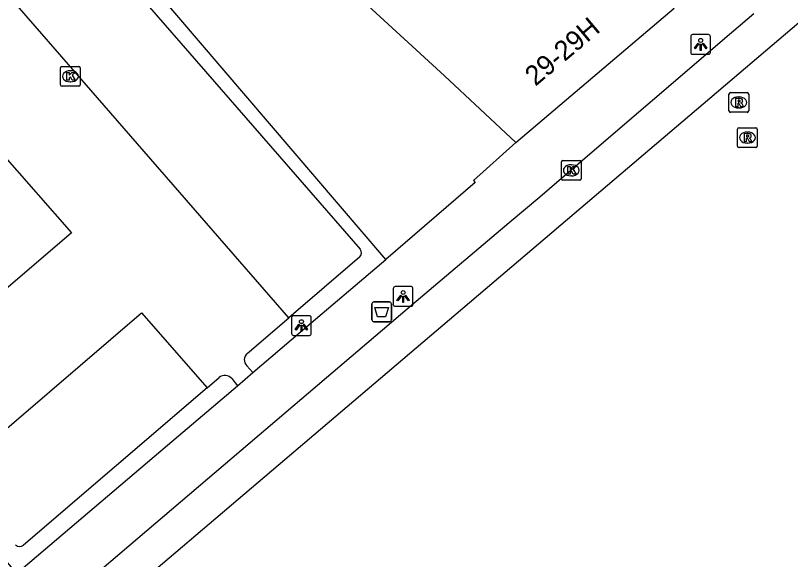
# Model space of a CAD drawing. Extents: x 161772 to 163123, y 383092 to 383917.
# Drawn here: x 162225.14 to 162264.38, y 383158.41 to 383185.94 of the extents above; entities that cross this region are included whole.
import ezdxf

# ---------------------------------------------------------------- set-up
doc = ezdxf.new("R2010")
doc.units = 0
for name, color, linetype in [('IMGEO_Afvalbak', 7, 'Continuous'), ('IMGEO_Groenvoorziening', 7, 'Continuous'), ('IMGEO_Hek', 7, 'Continuous'), ('IMGEO_Kolk', 7, 'Continuous'), ('IMGEO_Lichtpunt', 7, 'Continuous'), ('IMGEO_Pand', 7, 'Continuous'), ('IMGEO_Pand_nummerreeks', 7, 'Continuous'), ('IMGEO_Parkeervlak_open', 7, 'Continuous'), ('IMGEO_Rijbaan_lokaal_gesloten', 7, 'Continuous'), ('IMGEO_Rijbaan_lokaal_open', 7, 'Continuous'), ('IMGEO_Rioolput', 7, 'Continuous'), ('IMGEO_Voetpad_open', 7, 'Continuous')]:
    doc.layers.add(name, color=color, linetype=linetype)

msp = doc.modelspace()

# ---------------------------------------------------------------- linework, layer by layer
at = {"layer": 'IMGEO_Afvalbak'}
for p, q in [((162243.185, 383170.546), (162243.185, 383171.346)), ((162243.185, 383171.346), (162243.185, 383170.546)), ((162243.285, 383171.446), (162244.075, 383171.446)), ((162244.075, 383171.446), (162243.285, 383171.446)), ((162244.175, 383171.346), (162244.175, 383170.546)), ((162244.175, 383170.546), (162244.175, 383171.346)), ((162244.075, 383170.446), (162243.285, 383170.446)), ((162243.285, 383170.446), (162244.075, 383170.446))]:
    msp.add_line(p, q, dxfattribs=at)
msp.add_lwpolyline([(162243.328, 383171.16), (162244.032, 383171.16), (162243.883, 383170.69), (162243.477, 383170.69), (162243.328, 383171.16)], dxfattribs=at)
for centre, start, end in [((162243.285, 383171.346), 90, 180), ((162243.285, 383171.346), 90, 180), ((162244.075, 383171.346), 0, 90), ((162244.075, 383171.346), 360, 90), ((162243.285, 383170.546), 180, 270), ((162243.285, 383170.546), 180, 270), ((162244.075, 383170.546), 270, 0), ((162244.075, 383170.546), 270, 0)]:
    msp.add_arc(centre, 0.1, start, end, dxfattribs=at)
at = {"layer": 'IMGEO_Groenvoorziening'}
msp.add_lwpolyline([(162243.889, 383173.587), (162230.919, 383188.769), (162246.037, 383201.777)], dxfattribs=at)
at = {"layer": 'IMGEO_Hek'}
msp.add_lwpolyline([(162243.889, 383173.587), (162230.919, 383188.769), (162246.037, 383201.777)], dxfattribs=at)
at = {"layer": 'IMGEO_Kolk'}
for p, q in [((162227.423, 383182.439), (162227.423, 383183.291)), ((162227.498, 383183.365), (162228.35, 383183.365)), ((162227.911, 383183.145), (162227.936, 383183.145)), ((162228.424, 383183.291), (162228.424, 383182.439)), ((162227.934, 383182.585), (162227.909, 383182.585)), ((162228.35, 383182.365), (162227.498, 383182.365)), ((162252.781, 383177.68), (162252.781, 383178.532)), ((162252.856, 383178.606), (162253.708, 383178.606)), ((162253.269, 383178.386), (162253.294, 383178.386)), ((162253.782, 383178.532), (162253.782, 383177.68)), ((162253.708, 383177.606), (162252.856, 383177.606)), ((162253.292, 383177.826), (162253.267, 383177.826))]:
    msp.add_line(p, q, dxfattribs=at)
for points in [[(162227.423, 383182.439), (162227.423, 383183.291)], [(162227.498, 383183.365), (162228.35, 383183.365)], [(162227.744, 383183.065), (162227.867, 383183.065), (162227.867, 383182.914), (162227.997, 383183.065), (162228.161, 383183.065), (162228.015, 383182.914), (162228.168, 383182.665), (162228.016, 383182.665), (162227.931, 383182.829), (162227.867, 383182.762), (162227.867, 383182.665), (162227.744, 383182.665), (162227.744, 383183.065)], [(162228.424, 383183.291), (162228.424, 383182.439)], [(162228.35, 383182.365), (162227.498, 383182.365)], [(162252.781, 383177.68), (162252.781, 383178.532)], [(162252.856, 383178.606), (162253.708, 383178.606)], [(162253.102, 383178.306), (162253.225, 383178.306), (162253.225, 383178.155), (162253.355, 383178.306), (162253.519, 383178.306), (162253.373, 383178.155), (162253.526, 383177.906), (162253.374, 383177.906), (162253.289, 383178.07), (162253.225, 383178.003), (162253.225, 383177.906), (162253.102, 383177.906), (162253.102, 383178.306)], [(162253.782, 383178.532), (162253.782, 383177.68)], [(162253.708, 383177.606), (162252.856, 383177.606)]]:
    msp.add_lwpolyline(points, dxfattribs=at)
for centre, start, end in [((162227.5, 383183.289), 91.552, 178.448), ((162227.5, 383183.289), 91.552, 178.448), ((162228.348, 383183.289), 1.552, 88.448), ((162228.348, 383183.289), 1.552, 88.448), ((162227.5, 383182.441), 181.552, 268.448), ((162227.5, 383182.441), 181.552, 268.448), ((162228.348, 383182.441), 271.552, 358.448), ((162228.348, 383182.441), 271.552, 358.448), ((162252.858, 383178.53), 91.552, 178.448), ((162252.858, 383178.53), 91.552, 178.448), ((162253.706, 383178.53), 1.552, 88.448), ((162253.706, 383178.53), 1.552, 88.448), ((162252.858, 383177.682), 181.552, 268.448), ((162252.858, 383177.682), 181.552, 268.448), ((162253.706, 383177.682), 271.552, 358.448), ((162253.706, 383177.682), 271.552, 358.448)]:
    msp.add_arc(centre, 0.0765, start, end, dxfattribs=at)
for centre, major_axis, ratio, start_param, end_param in [((162227.91, 383182.865), (-0.387, 0.002), 0.722429, 4.712389, 7.853982), ((162227.935, 383182.865), (-0.39, 0.002), 0.717154, 1.570796, 4.712389), ((162253.268, 383178.106), (-0.387, 0.002), 0.722429, 4.712389, 7.853982), ((162253.293, 383178.106), (-0.39, 0.002), 0.717154, 1.570796, 4.712389)]:
    msp.add_ellipse(centre, major_axis=major_axis, ratio=ratio, start_param=start_param, end_param=end_param, dxfattribs=at)
at = {"layer": 'IMGEO_Lichtpunt'}
for p, q in [((162260.234, 383184.977), (162259.426, 383184.977)), ((162260.234, 383184.977), (162259.426, 383184.977)), ((162259.332, 383184.882), (162259.332, 383184.075)), ((162259.332, 383184.882), (162259.332, 383184.075)), ((162260.328, 383184.075), (162260.328, 383184.882)), ((162260.328, 383184.075), (162260.328, 383184.882)), ((162259.426, 383183.981), (162260.234, 383183.981)), ((162259.426, 383183.981), (162260.234, 383183.981)), ((162244.271, 383172.125), (162244.271, 383171.318)), ((162244.271, 383172.125), (162244.271, 383171.318)), ((162245.173, 383172.22), (162244.365, 383172.22)), ((162245.173, 383172.22), (162244.365, 383172.22)), ((162245.267, 383171.318), (162245.267, 383172.125)), ((162245.267, 383171.318), (162245.267, 383172.125)), ((162244.365, 383171.224), (162245.173, 383171.224)), ((162244.365, 383171.224), (162245.173, 383171.224)), ((162239.122, 383170.65), (162239.122, 383169.843)), ((162239.122, 383170.65), (162239.122, 383169.843)), ((162240.024, 383170.745), (162239.216, 383170.745)), ((162240.024, 383170.745), (162239.216, 383170.745)), ((162240.118, 383169.843), (162240.118, 383170.65)), ((162240.118, 383169.843), (162240.118, 383170.65)), ((162239.216, 383169.749), (162240.024, 383169.749)), ((162239.216, 383169.749), (162240.024, 383169.749))]:
    msp.add_line(p, q, dxfattribs=at)
for points in [[(162259.706, 383184.546), (162259.745, 383184.518), (162259.557, 383184.256), (162259.519, 383184.283), (162259.706, 383184.546)], [(162259.808, 383184.498), (162259.855, 383184.498), (162259.855, 383184.176), (162259.808, 383184.176), (162259.808, 383184.498)], [(162259.918, 383184.518), (162259.956, 383184.545), (162260.143, 383184.283), (162260.104, 383184.255), (162259.918, 383184.518)], [(162244.645, 383171.789), (162244.684, 383171.761), (162244.496, 383171.499), (162244.458, 383171.526), (162244.645, 383171.789)], [(162244.747, 383171.741), (162244.794, 383171.741), (162244.794, 383171.419), (162244.747, 383171.419), (162244.747, 383171.741)], [(162244.857, 383171.761), (162244.895, 383171.788), (162245.082, 383171.526), (162245.043, 383171.498), (162244.857, 383171.761)], [(162239.496, 383170.314), (162239.535, 383170.286), (162239.347, 383170.024), (162239.309, 383170.051), (162239.496, 383170.314)], [(162239.598, 383170.266), (162239.645, 383170.266), (162239.645, 383169.944), (162239.598, 383169.944), (162239.598, 383170.266)], [(162239.708, 383170.286), (162239.746, 383170.313), (162239.933, 383170.051), (162239.894, 383170.023), (162239.708, 383170.286)]]:
    msp.add_lwpolyline(points, dxfattribs=at)
for centre in [(162259.831, 383184.68), (162244.77, 383171.923), (162239.621, 383170.448)]:
    msp.add_circle(centre, 0.0994, dxfattribs=at)
for centre, start, end in [((162259.426, 383184.882), 90, 180), ((162259.426, 383184.882), 90, 180), ((162260.234, 383184.882), 0, 90), ((162260.234, 383184.882), 0, 90), ((162259.426, 383184.075), 180, 270), ((162259.426, 383184.075), 180, 270), ((162260.234, 383184.075), 270, 0), ((162260.234, 383184.075), 270, 360), ((162244.365, 383172.125), 90, 180), ((162244.365, 383172.125), 90, 180), ((162245.173, 383172.125), 0, 90), ((162245.173, 383172.125), 0, 90), ((162244.365, 383171.318), 180, 270), ((162244.365, 383171.318), 180, 270), ((162245.173, 383171.318), 270, 0), ((162245.173, 383171.318), 270, 360), ((162239.216, 383170.65), 90, 180), ((162239.216, 383170.65), 90, 180), ((162240.024, 383170.65), 0, 90), ((162240.024, 383170.65), 0, 90), ((162239.216, 383169.843), 180, 270), ((162239.216, 383169.843), 180, 270), ((162240.024, 383169.843), 270, 0), ((162240.024, 383169.843), 270, 360)]:
    msp.add_arc(centre, 0.0946, start, end, dxfattribs=at)
at = {"layer": 'IMGEO_Pand'}
for points in [[(162258.491, 383186.32), (162255.348, 383190.151), (162253.172, 383192.748), (162250.614, 383195.107), (162251.288, 383195.842), (162249.902, 383197.158), (162249.209, 383196.463), (162247.177, 383198.328), (162239.321, 383189.813), (162246.857, 383182.89), (162250.473, 383179.521)], [(162250.473, 383179.521), (162258.491, 383186.32)]]:
    msp.add_lwpolyline(points, dxfattribs=at)
at = {"layer": 'IMGEO_Parkeervlak_open'}
for points in [[(162225.69, 383193.555), (162242.586, 383174.121)], [(162242.567, 383173.705), (162238.988, 383170.647)], [(162234.843, 383167.096), (162225.551, 383159.132)]]:
    msp.add_lwpolyline(points, dxfattribs=at)
for centre, radius, start, end in [((162242.363, 383173.923), 0.298, 313.1404, 41.6294), ((162225.359, 383159.372), 0.307, 225.268, 308.559)]:
    msp.add_arc(centre, radius, start, end, dxfattribs=at)
at = {"layer": 'IMGEO_Rijbaan_lokaal_gesloten'}
for points in [[(162501.18, 383386.596), (162499.827, 383385.459), (162477.128, 383365.985), (162459.036, 383350.651), (162175.227, 383109.464), (162171.607, 383105.25), (162169.364, 383100.909), (162168.706, 383099.067), (162168.602, 383098.586)], [(162262.524, 383186.021), (162261.398, 383185.06), (162253.282, 383178.106), (162251.683, 383176.756), (162250.138, 383175.449), (162245.425, 383171.464), (162239.188, 383166.147), (162228.269, 383156.857)]]:
    msp.add_lwpolyline(points, dxfattribs=at)
at = {"layer": 'IMGEO_Rijbaan_lokaal_open'}
for points in [[(162238.988, 383170.647), (162226.478, 383185.013), (162221.261, 383191.003), (162225.036, 383194.323), (162225.69, 383193.555)], [(162224.284, 383179.006), (162224.361, 383179.067), (162227.97, 383174.951), (162218.59, 383166.911)], [(162222.072, 383162.793), (162231.514, 383170.901), (162234.843, 383167.096)], [(162236.877, 383168.844), (162238.988, 383170.647)], [(162237.164, 383167.873), (162236.857, 383168.211)], [(162236.381, 383167.208), (162237.164, 383167.873)], [(162234.843, 383167.096), (162235.453, 383167.619)], [(162236.096, 383167.566), (162236.381, 383167.208)]]:
    msp.add_lwpolyline(points, dxfattribs=at)
for centre, radius, start, end in [((162237.143, 383168.519), 0.42, 129.2462, 227.1345), ((162235.749, 383167.281), 0.449, 39.4224, 131.1536)]:
    msp.add_arc(centre, radius, start, end, dxfattribs=at)
at = {"layer": 'IMGEO_Rioolput'}
for p, q in [((162261.263, 383181.115), (162261.263, 383181.967)), ((162261.338, 383182.041), (162262.19, 383182.041)), ((162261.751, 383181.821), (162261.776, 383181.821)), ((162262.264, 383181.967), (162262.264, 383181.115)), ((162262.19, 383181.041), (162261.338, 383181.041)), ((162261.774, 383181.261), (162261.749, 383181.261)), ((162261.774, 383180.262), (162262.626, 383180.262)), ((162261.699, 383179.336), (162261.699, 383180.188)), ((162262.187, 383180.042), (162262.212, 383180.042)), ((162262.7, 383180.188), (162262.7, 383179.336)), ((162262.21, 383179.482), (162262.185, 383179.482)), ((162262.626, 383179.262), (162261.774, 383179.262))]:
    msp.add_line(p, q, dxfattribs=at)
for points in [[(162261.263, 383181.115), (162261.263, 383181.967)], [(162261.338, 383182.041), (162262.19, 383182.041)], [(162262.264, 383181.967), (162262.264, 383181.115)], [(162261.852, 383181.739), (162261.6, 383181.741), (162261.6, 383181.341)], [(162261.6, 383181.341), (162261.724, 383181.341), (162261.724, 383181.503), (162261.735, 383181.503)], [(162261.778, 383181.66), (162261.724, 383181.66), (162261.724, 383181.579)], [(162261.724, 383181.579), (162261.776, 383181.579)], [(162261.782, 383181.474), (162261.853, 383181.341), (162261.993, 383181.341), (162261.928, 383181.467)], [(162262.19, 383181.041), (162261.338, 383181.041)], [(162261.774, 383180.262), (162262.626, 383180.262)], [(162261.699, 383179.336), (162261.699, 383180.188)], [(162262.288, 383179.96), (162262.036, 383179.962), (162262.036, 383179.562)], [(162262.214, 383179.881), (162262.16, 383179.881), (162262.16, 383179.8)], [(162262.7, 383180.188), (162262.7, 383179.336)], [(162262.036, 383179.562), (162262.16, 383179.562), (162262.16, 383179.724), (162262.171, 383179.724)], [(162262.16, 383179.8), (162262.212, 383179.8)], [(162262.218, 383179.695), (162262.289, 383179.562), (162262.429, 383179.562), (162262.364, 383179.688)], [(162262.626, 383179.262), (162261.774, 383179.262)]]:
    msp.add_lwpolyline(points, dxfattribs=at)
for centre, radius, start, end in [((162261.34, 383181.965), 0.0765, 91.552, 178.448), ((162261.34, 383181.965), 0.0765, 91.552, 178.448), ((162262.188, 383181.965), 0.0765, 1.552, 88.448), ((162262.188, 383181.965), 0.0765, 1.552, 88.448), ((162261.734, 383181.45), 0.0533, 26.0293, 88.6989), ((162261.76, 383181.768), 0.19, 274.7715, 282.9687), ((162261.784, 383181.564), 0.0964, 77.0061, 93.1865), ((162261.798, 383181.621), 0.0378, 276.6634, 79.6772), ((162261.851, 383181.629), 0.109, 350.3612, 89.416), ((162261.849, 383181.629), 0.112, 277.5842, 350.9817), ((162261.833, 383181.414), 0.108, 29.5134, 73.7905), ((162261.34, 383181.117), 0.0765, 181.552, 268.448), ((162261.34, 383181.117), 0.0765, 181.552, 268.448), ((162262.188, 383181.117), 0.0765, 271.552, 358.448), ((162262.188, 383181.117), 0.0765, 271.552, 358.448), ((162261.776, 383180.186), 0.0765, 91.552, 178.448), ((162261.776, 383180.186), 0.0765, 91.552, 178.448), ((162262.624, 383180.186), 0.0765, 1.552, 88.448), ((162262.624, 383180.186), 0.0765, 1.552, 88.448), ((162262.22, 383179.785), 0.0964, 77.0061, 93.1865), ((162262.234, 383179.842), 0.0378, 276.6634, 79.6772), ((162262.287, 383179.85), 0.109, 350.3612, 89.416), ((162262.17, 383179.671), 0.0533, 26.0293, 88.6989), ((162262.196, 383179.989), 0.19, 274.7715, 282.9687), ((162262.285, 383179.85), 0.112, 277.5842, 350.9817), ((162262.269, 383179.635), 0.108, 29.5134, 73.7905), ((162261.776, 383179.338), 0.0765, 181.552, 268.448), ((162261.776, 383179.338), 0.0765, 181.552, 268.448), ((162262.624, 383179.338), 0.0765, 271.552, 358.448), ((162262.624, 383179.338), 0.0765, 271.552, 358.448)]:
    msp.add_arc(centre, radius, start, end, dxfattribs=at)
for centre, major_axis, ratio, start_param, end_param in [((162261.75, 383181.541), (-0.387, 0.002), 0.722429, 4.712389, 7.853982), ((162261.775, 383181.541), (-0.39, 0.002), 0.717154, 1.570796, 4.712389), ((162262.186, 383179.762), (-0.387, 0.002), 0.722429, 4.712389, 7.853982), ((162262.211, 383179.762), (-0.39, 0.002), 0.717154, 1.570796, 4.712389)]:
    msp.add_ellipse(centre, major_axis=major_axis, ratio=ratio, start_param=start_param, end_param=end_param, dxfattribs=at)
at = {"layer": 'IMGEO_Voetpad_open'}
for points in [[(162250.473, 383179.521), (162248.325, 383177.589), (162248.421, 383177.492), (162243.889, 383173.587)], [(162237.164, 383167.873), (162239.561, 383169.91), (162243.889, 383173.587)], [(162223.781, 383159.361), (162225.202, 383157.707), (162232.846, 383164.203), (162236.381, 383167.208)]]:
    msp.add_lwpolyline(points, dxfattribs=at)

# ---------------------------------------------------------------- texts
at = {"layer": 'IMGEO_Pand_nummerreeks'}
msp.add_text('29-29H', height=1, rotation=40.2961, dxfattribs=at).set_placement((162251.469, 383182.332))

doc.saveas('drawing.dxf')
